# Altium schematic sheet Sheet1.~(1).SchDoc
size A4
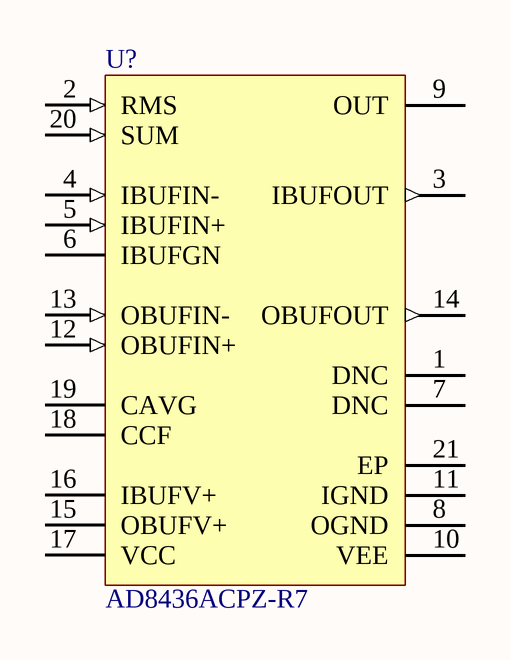
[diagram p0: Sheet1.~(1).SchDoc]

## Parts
U?  AD8436ACPZ-R7  [ADI-CP-20-10_M]

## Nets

Not connected (* = marked no-connect by the designer): U? 1(DNC) 2(RMS) 3(IBUFOUT) 4(IBUFIN-) 5(IBUFIN+) 6(IBUFGN) 7(DNC) 8(OGND) 9(OUT) 10(VEE) 11(IGND) 12(OBUFIN+) 13(OBUFIN-) 14(OBUFOUT) 15(OBUFV+) 16(IBUFV+) 17(VCC) 18(CCF) 19(CAVG) 20(SUM) 21(EP)

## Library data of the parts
U? = CMP-0527-00003-3: Low Cost, Low Power, True RMS-to-DC Converter, 4.8 to 36 V Single Supply, -40 to 125 degC, 20-Pin QFN (CP-20-10); Manufacturer: Analog Devices; -3dB Bandwidth: 950 KHz; Max Vin (V-rms): 3 V rms; V Span (min): 4.8 V; Supply Current: 300 uA; V Span (max): 36 V; Error (%@ CF: 3)=0.5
